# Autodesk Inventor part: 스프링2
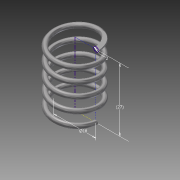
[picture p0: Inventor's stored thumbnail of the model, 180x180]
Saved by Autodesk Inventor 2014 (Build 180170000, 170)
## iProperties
Created: 2016-10
Part Number: 스프링2
Material: Steel, Carbon
Document SubType Name: Modeling
Designer: user
Mass: 6.87503 g
Surface Area: 17.7418 cm^2
Volume: 0.873574 cm^3
Density: 7.87 g/cm^3
Appearance: Semi-Polished
Author: user
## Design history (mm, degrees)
sketch "Sketch1"
  geometry: L1 (0, 0)-(-9, 0); L2 (-9, 0)-(-9, -26); L3 (-9, -26)-(0, -26); L4 (0, -26)-(0, 0); C1 r 1 at (-9, 0)
  constraints: 8 end point, 2 parallel, 1 centre point, 1 coincident, 1 horizontal, 1 perpendicular
  dimensions: "d0" = 26 distance of L1.end L2.end (derived); "d1" = 2 diameter of C1; "d2" = 18 diameter of L2 L4
coil "Coil1" pitch "d3" = 10; turns "d5" = 5; dims "d4" = 26 (= d0), "d6" = 0, angle "d7" = 90 deg, angle "d8" = 90 deg, "d9" = 0, "d10" = 0
sketch "Sketch2"
  geometry: L1 (10, 0)-(8, 0) reference; L2 (10, 0)-(8, 0) reference; 1 further point
  constraints: 2 horizontal alignment
extrude "Extrusion1" cut sketch "Sketch2" stored distance "d11" = 10; taper "d12" = 0 deg
workplane "Work Plane1"
sketch "Sketch3"
  geometry: L1 (-1, 0)-(1, 0) reference; 1 further point
  constraints: 1 horizontal alignment
extrude "Extrusion2" cut sketch "Sketch3" stored distance "d14" = 10; taper "d15" = 0 deg
body "Solid1"
node "Project Cut Edges1"
node "Project Cut Edges2"
node "Project Cut Edges3"
other parameters: "d13" = 90 deg
